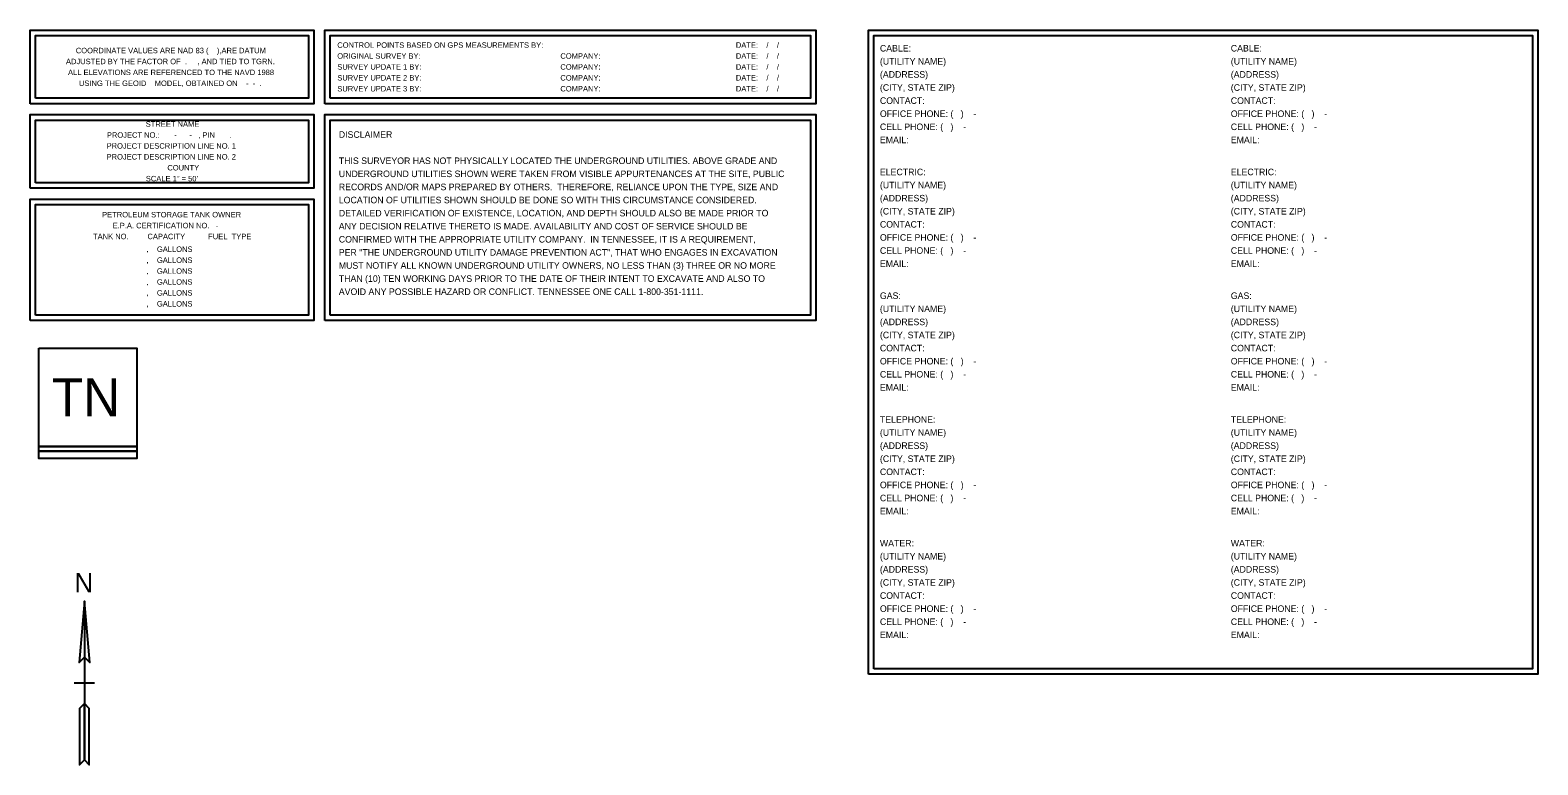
# Model space of a CAD drawing. Extents: x 514 to 1896, y 344 to 1017.
import ezdxf

# ---------------------------------------------------------------- set-up
doc = ezdxf.new("R2010")
doc.units = 0
for name, color, linetype in [('SUR - CTRL - Text', 7, 'Continuous'), ('SUR - Project Information and Notes', 7, 'Continuous'), ('SUR - UTL - Owners', 7, 'Continuous')]:
    doc.layers.add(name, color=color, linetype=linetype)

msp = doc.modelspace()

# ---------------------------------------------------------------- linework, layer by layer
at = {"layer": 'SUR - CTRL - Text'}
for points in [[(514.3, 949.9), (514.3, 1017.3), (774.3, 1017.3), (774.3, 949.9)], [(519.3, 954.9), (519.3, 1012.3), (769.3, 1012.3), (769.3, 954.9)], [(784.3, 949.9), (784.3, 1017.3), (1234.3, 1017.3), (1234.3, 949.9)], [(789.3, 954.9), (789.3, 1012.3), (1229.3, 1012.3), (1229.3, 954.9)]]:
    msp.add_lwpolyline(points, close=True, dxfattribs=at)
at = {"layer": 'SUR - Project Information and Notes'}
for p, q in [((564, 418.9), (554.5, 418.9)), ((573.4, 418.9), (564, 418.9))]:
    msp.add_line(p, q, dxfattribs=at)
for points in [[(514.3, 872.5), (514.3, 939.9), (774.3, 939.9), (774.3, 872.5)], [(519.3, 877.5), (519.3, 934.9), (769.3, 934.9), (769.3, 877.5)], [(514.3, 751.1), (514.3, 862.5), (774.3, 862.5), (774.3, 751.1)], [(519.3, 756.1), (519.3, 857.5), (769.3, 857.5), (769.3, 756.1)], [(522.1, 725.8), (612.1, 725.8), (612.1, 635.8), (522.1, 635.8)], [(522.1, 725.8), (612.1, 725.8), (612.1, 635.8), (522.1, 635.8)], [(522.1, 635.8), (612.1, 635.8), (612.1, 631.3), (522.1, 631.3)], [(522.1, 635.8), (612.1, 635.8), (612.1, 631.3), (522.1, 631.3)], [(522.1, 631.3), (612.1, 631.3), (612.1, 624.6), (522.1, 624.6)], [(522.1, 631.3), (612.1, 631.3), (612.1, 624.6), (522.1, 624.6)], [(564, 442.5), (568.9, 437.6), (564, 493.9)], [(559.4, 343.9), (564, 348.5), (564, 400.2), (559.4, 395.7)]]:
    msp.add_lwpolyline(points, close=True, dxfattribs=at)
msp.add_lwpolyline([(564, 493.9), (559.1, 437.6), (564, 442.5), (568.9, 437.6), (564, 493.9), (564, 348.5), (568.5, 343.9), (568.5, 395.7), (564, 400.2), (559.4, 395.7), (559.4, 343.9), (564, 348.5)], dxfattribs=at)
at = {"layer": 'SUR - UTL - Owners'}
for points in [[(1282.4, 426.9), (1282.4, 1017.3), (1895.7, 1017.3), (1895.7, 426.9)], [(1287.4, 431.9), (1287.4, 1012.3), (1890.7, 1012.3), (1890.7, 431.9)], [(784.3, 751.1), (784.3, 939.9), (1234.3, 939.9), (1234.3, 751.1)], [(789.3, 756.1), (789.3, 934.9), (1229.3, 934.9), (1229.3, 756.1)]]:
    msp.add_lwpolyline(points, close=True, dxfattribs=at)

# ---------------------------------------------------------------- texts
at = {"layer": 'SUR - CTRL - Text'}
for s, p in [('COORDINATE VALUES ARE NAD 83 (    ),ARE DATUM', (556.1, 996.1)), ('ORIGINAL SURVEY BY:                               ', (795.7, 991.1)), ('CONTROL POINTS BASED ON GPS MEASUREMENTS BY:                                            ', (795.7, 1001.1)), ('COMPANY:                               ', (1000.1, 991.1)), ('DATE:    /    /   ', (1160.9, 1001.1)), ('DATE:    /    /    ', (1160.9, 991.1)), ('ADJUSTED BY THE FACTOR OF  .     , AND TIED TO TGRN. ', (547.1, 986.1)), ('ALL ELEVATIONS ARE REFERENCED TO THE NAVD 1988', (549, 976.1)), ('SURVEY UPDATE 1 BY:                               ', (795.7, 981.1)), ('COMPANY:                               ', (1000.1, 981.1)), ('DATE:    /    /     ', (1160.9, 981.1)), ('USING THE GEOID    MODEL, OBTAINED ON    -  -  .', (559, 966.1)), ('SURVEY UPDATE 2 BY:                               ', (795.7, 971.1)), ('COMPANY:                               ', (1000.1, 971.1)), ('DATE:    /    /     ', (1160.9, 971.1)), ('SURVEY UPDATE 3 BY:                               ', (795.7, 961.1)), ('COMPANY:                               ', (1000.1, 961.1)), ('DATE:    /    /    ', (1160.9, 961.1))]:
    msp.add_text(s, height=5, dxfattribs=at).set_placement(p)
at = {"layer": 'SUR - Project Information and Notes'}
for s, height, p in [('            STREET NAME           ', 5, (597.2, 928.7)), ('  PROJECT DESCRIPTION LINE NO. 1  ', 5, (580.5, 908.7)), ('PROJECT NO.:       -      -   , PIN       .  ', 5, (584.6, 918.7)), ('  PROJECT DESCRIPTION LINE NO. 2  ', 5, (580.5, 898.7)), ('           COUNTY', 5, (618.9, 888.7)), ('SCALE 1" = 50\'', 5, (620.3, 878.7)), (' PETROLEUM STORAGE TANK OWNER ', 5, (578.3, 845.7)), ('TANK NO.         CAPACITY           FUEL  TYPE', 5, (571.9, 825.7)), ('E.P.A. CERTIFICATION NO.   -      ', 5, (589.9, 835.7)), ('  ,    GALLONS', 5, (617, 814)), ('   ,    GALLONS', 5, (615.1, 804)), ('  ,    GALLONS', 5, (617, 794)), ('  ,    GALLONS', 5, (617, 784)), ('  ,    GALLONS', 5, (617, 774)), ('  ,    GALLONS', 5, (617, 764)), ('TN', 35, (534.3, 663.3)), ('N', 17.7, (554.9, 502))]:
    msp.add_text(s, height=height, dxfattribs=at).set_placement(p)
at = {"layer": 'SUR - UTL - Owners'}
for s, p in [('CABLE:', (1292.9, 997.7)), ('CABLE:', (1614.4, 997.7)), ('(UTILITY NAME)                                    ', (1292.9, 985.7)), ('(UTILITY NAME)                                    ', (1614.4, 985.7)), ('(ADDRESS)                                               ', (1292.9, 973.7)), ('(CITY, STATE ZIP)                                 ', (1292.9, 961.7)), ('(ADDRESS)                                               ', (1614.4, 973.7)), ('(CITY, STATE ZIP)                                 ', (1614.4, 961.7)), ('CONTACT:                                                   ', (1292.9, 949.7)), ('CONTACT:                                                   ', (1614.4, 949.7)), ('OFFICE PHONE: (   )    -    ', (1292.9, 937.7)), ('OFFICE PHONE: (   )    -    ', (1614.4, 937.7)), ('CELL PHONE: (   )    -    ', (1292.9, 925.7)), ('CELL PHONE: (   )    -    ', (1614.4, 925.7)), ('DISCLAIMER', (797.1, 918.6)), ('EMAIL:                                                    ', (1292.9, 913.7)), ('EMAIL:                                                    ', (1614.4, 913.7)), ('THIS SURVEYOR HAS NOT PHYSICALLY LOCATED THE UNDERGROUND UTILITIES. ABOVE GRADE AND ', (797.1, 894.6)), ('UNDERGROUND UTILITIES SHOWN WERE TAKEN FROM VISIBLE APPURTENANCES AT THE SITE, PUBLIC ', (797.1, 882.6)), ('ELECTRIC:', (1292.9, 884.3)), ('ELECTRIC:', (1614.4, 884.3)), ('RECORDS AND/OR MAPS PREPARED BY OTHERS.  THEREFORE, RELIANCE UPON THE TYPE, SIZE AND ', (797.1, 870.6)), ('(UTILITY NAME)                                    ', (1292.9, 872.3)), ('(UTILITY NAME)                                    ', (1614.4, 872.3)), ('LOCATION OF UTILITIES SHOWN SHOULD BE DONE SO WITH THIS CIRCUMSTANCE CONSIDERED.', (797.1, 858.6)), ('(ADDRESS)                                         ', (1292.9, 860.3)), ('(ADDRESS)                                         ', (1614.4, 860.3)), ('DETAILED VERIFICATION OF EXISTENCE, LOCATION, AND DEPTH SHOULD ALSO BE MADE PRIOR TO ', (797.1, 846.6)), ('(CITY, STATE ZIP)                                 ', (1292.9, 848.3)), ('(CITY, STATE ZIP)                                 ', (1614.4, 848.3)), ('ANY DECISION RELATIVE THERETO IS MADE. AVAILABILITY AND COST OF SERVICE SHOULD BE ', (797.1, 834.6)), ('CONTACT:                                                   ', (1292.9, 836.3)), ('OFFICE PHONE: (   )    -    ', (1292.9, 824.3)), ('CONTACT:                                                   ', (1614.4, 836.3)), ('OFFICE PHONE: (   )    -    ', (1614.4, 824.3)), ('CONFIRMED WITH THE APPROPRIATE UTILITY COMPANY.  IN TENNESSEE, IT IS A REQUIREMENT, ', (797.1, 822.6)), ('PER "THE UNDERGROUND UTILITY DAMAGE PREVENTION ACT", THAT WHO ENGAGES IN EXCAVATION ', (797.1, 810.6)), ('CELL PHONE: (   )    -    ', (1292.9, 812.3)), ('CELL PHONE: (   )    -    ', (1614.4, 812.3)), ('MUST NOTIFY ALL KNOWN UNDERGROUND UTILITY OWNERS, NO LESS THAN (3) THREE OR NO MORE ', (797.1, 798.6)), ('EMAIL:                                                    ', (1292.9, 800.3)), ('EMAIL:                                                    ', (1614.4, 800.3)), ('THAN (10) TEN WORKING DAYS PRIOR TO THE DATE OF THEIR INTENT TO EXCAVATE AND ALSO TO ', (797.1, 786.6)), ('AVOID ANY POSSIBLE HAZARD OR CONFLICT. TENNESSEE ONE CALL 1-800-351-1111.', (797.1, 774.6)), ('GAS:', (1292.9, 770.9)), ('GAS:', (1614.4, 770.9)), ('(UTILITY NAME)                                    ', (1292.9, 758.9)), ('(UTILITY NAME)                                    ', (1614.4, 758.9)), ('(ADDRESS)                                         ', (1292.9, 746.9)), ('(ADDRESS)                                         ', (1614.4, 746.9)), ('(CITY, STATE ZIP)                                 ', (1292.9, 734.9)), ('(CITY, STATE ZIP)                                 ', (1614.4, 734.9)), ('CONTACT:                                                   ', (1292.9, 722.9)), ('CONTACT:                                                   ', (1614.4, 722.9)), ('OFFICE PHONE: (   )    -    ', (1292.9, 710.9)), ('CELL PHONE: (   )    -    ', (1292.9, 698.9)), ('OFFICE PHONE: (   )    -    ', (1614.4, 710.9)), ('CELL PHONE: (   )    -    ', (1614.4, 698.9)), ('EMAIL:                                                    ', (1292.9, 686.9)), ('EMAIL:                                                    ', (1614.4, 686.9)), ('TELEPHONE:', (1292.9, 657.5)), ('TELEPHONE:', (1614.4, 657.5)), ('(UTILITY NAME)                                    ', (1292.9, 645.5)), ('(UTILITY NAME)                                    ', (1614.4, 645.5)), ('(ADDRESS)                                         ', (1292.9, 633.5)), ('(ADDRESS)                                         ', (1614.4, 633.5)), ('(CITY, STATE ZIP)                                 ', (1292.9, 621.5)), ('(CITY, STATE ZIP)                                 ', (1614.4, 621.5)), ('CONTACT:                                                   ', (1292.9, 609.5)), ('CONTACT:                                                   ', (1614.4, 609.5)), ('OFFICE PHONE: (   )    -    ', (1292.9, 597.5)), ('OFFICE PHONE: (   )    -    ', (1614.4, 597.5)), ('CELL PHONE: (   )    -    ', (1292.9, 585.5)), ('CELL PHONE: (   )    -    ', (1614.4, 585.5)), ('EMAIL:                                                    ', (1292.9, 573.5)), ('EMAIL:                                                    ', (1614.4, 573.5)), ('WATER:', (1292.9, 544.1)), ('WATER:', (1614.4, 544.1)), ('(UTILITY NAME)                                    ', (1292.9, 532.1)), ('(ADDRESS)                                         ', (1292.9, 520.1)), ('(UTILITY NAME)                                    ', (1614.4, 532.1)), ('(ADDRESS)                                         ', (1614.4, 520.1)), ('(CITY, STATE ZIP)                                 ', (1292.9, 508.1)), ('(CITY, STATE ZIP)                                 ', (1614.4, 508.1)), ('CONTACT:                                                   ', (1292.9, 496.1)), ('CONTACT:                                                   ', (1614.4, 496.1)), ('OFFICE PHONE: (   )    -    ', (1292.9, 484.1)), ('OFFICE PHONE: (   )    -    ', (1614.4, 484.1)), ('CELL PHONE: (   )    -    ', (1292.9, 472.1)), ('CELL PHONE: (   )    -    ', (1614.4, 472.1)), ('EMAIL:                                                    ', (1292.9, 460.1)), ('EMAIL:                                                    ', (1614.4, 460.1))]:
    msp.add_text(s, height=6, dxfattribs=at).set_placement(p)

doc.saveas('drawing.dxf')
